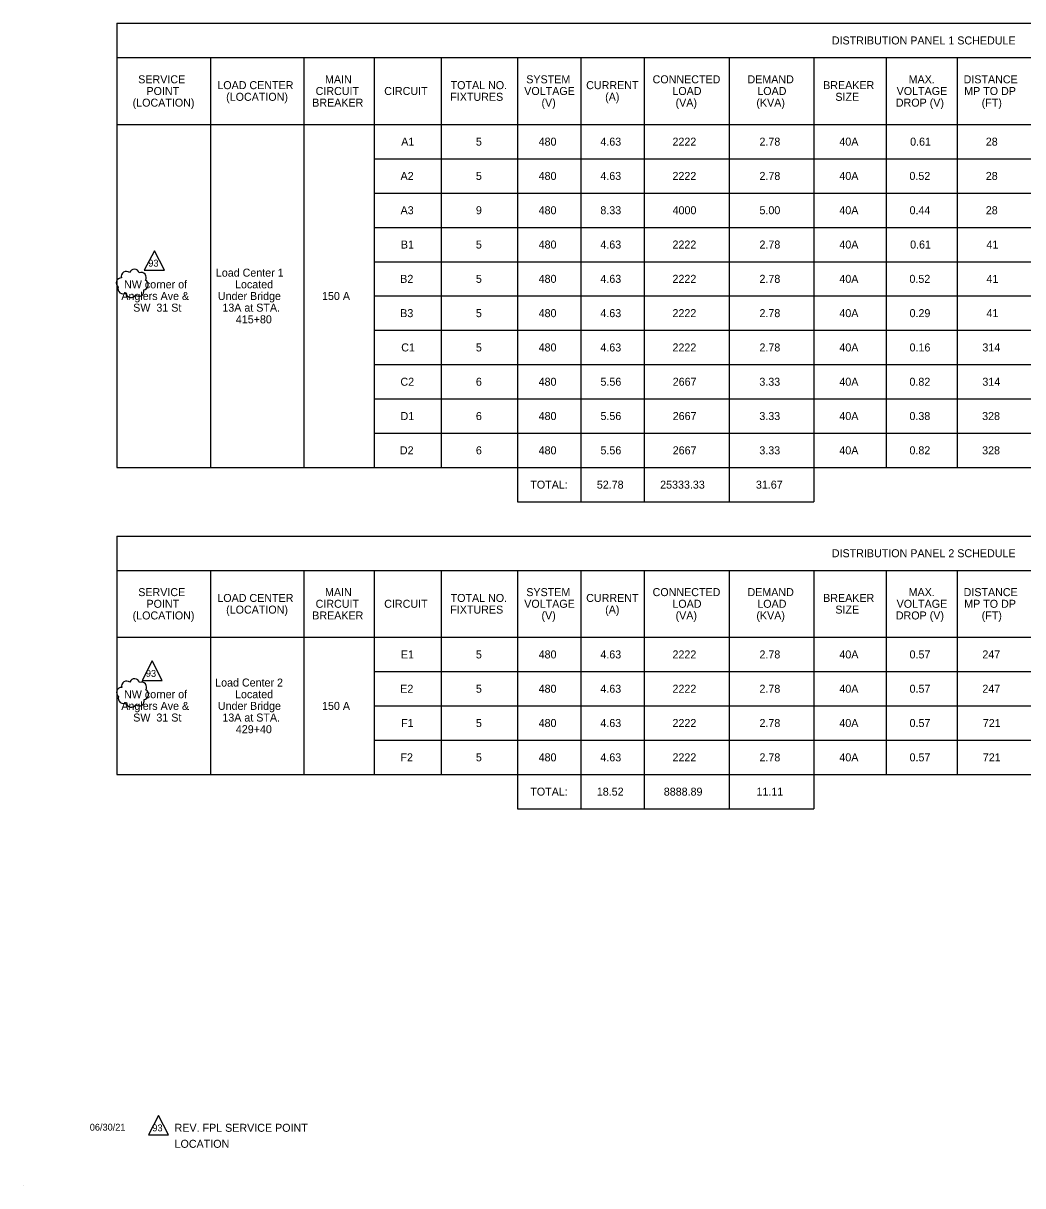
# Model space of a CAD drawing. Extents: x -0.6 to 15.3, y -0.9 to 9.3.
# Drawn here: x -0.55 to 8.19, y -0.9 to 9.27 of the extents above; entities that cross this region are included whole.
import ezdxf

# ---------------------------------------------------------------- set-up
doc = ezdxf.new("R2010")
doc.units = 0
for name, color, linetype in [('AdhocPoint_dp', 7, 'Continuous'), ('Cloud_dp', 7, 'Continuous'), ('SumBoxBorder_dp', 7, 'Continuous'), ('SumBoxLines_dp', 7, 'Continuous'), ('TextLabel', 7, 'Continuous'), ('TextMinor', 7, 'Continuous')]:
    doc.layers.add(name, color=color, linetype=linetype)

msp = doc.modelspace()

# ---------------------------------------------------------------- linework, layer by layer
at = {"layer": 'AdhocPoint_dp'}
msp.add_line((-0.55, -0.9), (-0.55, -0.9), dxfattribs=at)
at = {"layer": 'Cloud_dp'}
for points in [[(0.597, 7.278), (0.509, 7.109), (0.685, 7.109)], [(0.577, 3.69), (0.489, 3.52), (0.665, 3.52)], [(0.633, -0.285), (0.545, -0.454), (0.721, -0.454)]]:
    msp.add_lwpolyline(points, close=True, dxfattribs=at)
for centre, radius, start, end in [((0.308, 6.996), 0.0445, 88.1066, 233.1066), ((0.352, 7.053), 0.0445, 50.9029, 195.9029), ((0.422, 7.072), 0.0445, 15.0691, 160.0691), ((0.482, 7.043), 0.0445, 327.4514, 112.4514), ((0.499, 6.98), 0.0445, 276.583, 61.583), ((0.323, 6.946), 0.0446, 160.4952, 305.4952), ((0.461, 6.924), 0.0445, 229.7011, 14.7011), ((0.394, 6.913), 0.0445, 184.2975, 329.2975), ((0.311, 3.414), 0.0445, 88.1066, 233.1066), ((0.355, 3.47), 0.0445, 50.9029, 195.9029), ((0.425, 3.49), 0.0445, 15.0691, 160.0691), ((0.485, 3.46), 0.0445, 327.4514, 112.4514), ((0.326, 3.363), 0.0446, 160.4952, 305.4952), ((0.502, 3.397), 0.0445, 276.583, 61.583), ((0.397, 3.33), 0.0445, 184.2975, 329.2975), ((0.464, 3.341), 0.0445, 229.7011, 14.7011)]:
    msp.add_arc(centre, radius, start, end, dxfattribs=at)
at = {"layer": 'SumBoxBorder_dp'}
for p, q in [((0.27, 9.267), (14.573, 9.267)), ((0.27, 9.267), (0.27, 5.382)), ((0.27, 8.967), (14.573, 8.967)), ((0.27, 5.382), (14.573, 5.382)), ((0.27, 5.382), (14.573, 5.382)), ((3.773, 5.382), (3.773, 5.082)), ((6.368, 5.382), (6.368, 5.082)), ((6.368, 5.382), (6.368, 5.082)), ((3.773, 5.082), (6.368, 5.082)), ((3.773, 5.082), (6.368, 5.082)), ((0.27, 4.782), (14.573, 4.782)), ((0.27, 4.782), (0.27, 2.697)), ((0.27, 4.482), (14.573, 4.482)), ((0.27, 4.482), (14.573, 4.482)), ((0.27, 2.697), (14.573, 2.697)), ((0.27, 2.697), (14.573, 2.697)), ((3.773, 2.697), (3.773, 2.397)), ((6.368, 2.697), (6.368, 2.397)), ((6.368, 2.697), (6.368, 2.397)), ((3.773, 2.397), (6.368, 2.397))]:
    msp.add_line(p, q, dxfattribs=at)
at = {"layer": 'SumBoxLines_dp'}
for p, q in [((1.088, 8.967), (1.088, 5.382)), ((1.088, 8.967), (1.088, 5.382)), ((1.905, 8.967), (1.905, 5.382)), ((1.905, 8.967), (1.905, 5.382)), ((2.52, 8.967), (2.52, 5.382)), ((2.52, 8.967), (2.52, 5.382)), ((3.105, 8.967), (3.105, 5.382)), ((3.105, 8.967), (3.105, 5.382)), ((3.773, 8.967), (3.773, 5.382)), ((3.773, 8.967), (3.773, 5.382)), ((4.328, 8.967), (4.328, 5.082)), ((4.328, 8.967), (4.328, 5.082)), ((4.883, 8.967), (4.883, 5.082)), ((4.883, 8.967), (4.883, 5.082)), ((5.625, 8.967), (5.625, 5.082)), ((5.625, 8.967), (5.625, 5.082)), ((6.368, 8.967), (6.368, 5.382)), ((6.368, 8.967), (6.368, 5.382)), ((6.998, 8.967), (6.998, 5.382)), ((6.998, 8.967), (6.998, 5.382)), ((7.62, 8.967), (7.62, 5.382)), ((7.62, 8.967), (7.62, 5.382)), ((0.27, 8.382), (14.573, 8.382)), ((0.27, 8.382), (14.573, 8.382)), ((2.52, 8.082), (14.573, 8.082)), ((2.52, 8.082), (14.573, 8.082)), ((2.52, 7.782), (14.573, 7.782)), ((2.52, 7.782), (14.573, 7.782)), ((2.52, 7.482), (14.573, 7.482)), ((2.52, 7.482), (14.573, 7.482)), ((2.52, 7.182), (14.573, 7.182)), ((2.52, 7.182), (14.573, 7.182)), ((2.52, 6.882), (14.573, 6.882)), ((2.52, 6.882), (14.573, 6.882)), ((2.52, 6.582), (14.573, 6.582)), ((2.52, 6.582), (14.573, 6.582)), ((2.52, 6.282), (14.573, 6.282)), ((2.52, 6.282), (14.573, 6.282)), ((2.52, 5.982), (14.573, 5.982)), ((2.52, 5.982), (14.573, 5.982)), ((2.52, 5.682), (14.573, 5.682)), ((2.52, 5.682), (14.573, 5.682)), ((1.088, 4.482), (1.088, 2.697)), ((1.088, 4.482), (1.088, 2.697)), ((1.905, 4.482), (1.905, 2.697)), ((1.905, 4.482), (1.905, 2.697)), ((2.52, 4.482), (2.52, 2.697)), ((2.52, 4.482), (2.52, 2.697)), ((3.105, 4.482), (3.105, 2.697)), ((3.105, 4.482), (3.105, 2.697)), ((3.773, 4.482), (3.773, 2.697)), ((3.773, 4.482), (3.773, 2.697)), ((4.328, 4.482), (4.328, 2.397)), ((4.328, 4.482), (4.328, 2.397)), ((4.883, 4.482), (4.883, 2.397)), ((4.883, 4.482), (4.883, 2.397)), ((5.625, 4.482), (5.625, 2.397)), ((5.625, 4.482), (5.625, 2.397)), ((6.368, 4.482), (6.368, 2.697)), ((6.368, 4.482), (6.368, 2.697)), ((6.998, 4.482), (6.998, 2.697)), ((6.998, 4.482), (6.998, 2.697)), ((7.62, 4.482), (7.62, 2.697)), ((7.62, 4.482), (7.62, 2.697)), ((0.27, 3.897), (14.573, 3.897)), ((0.27, 3.897), (14.573, 3.897)), ((2.52, 3.597), (14.573, 3.597)), ((2.52, 3.597), (14.573, 3.597)), ((2.52, 3.297), (14.573, 3.297)), ((2.52, 3.297), (14.573, 3.297)), ((2.52, 2.997), (14.573, 2.997)), ((2.52, 2.997), (14.573, 2.997))]:
    msp.add_line(p, q, dxfattribs=at)

# ---------------------------------------------------------------- texts
at = {"layer": 'Cloud_dp'}
for p in [(0.544, 7.139), (0.523, 3.551), (0.58, -0.424)]:
    msp.add_text('93', height=0.06, rotation=0, dxfattribs=at).set_placement(p)
at = {"layer": 'TextLabel'}
for s, p in [('DISTRIBUTION PANEL 1 SCHEDULE', (6.524, 9.082)), ('SERVICE', (0.456, 8.742)), ('LOAD CENTER', (1.148, 8.691)), ('MAIN', (2.09, 8.742)), ('TOTAL NO.', (3.189, 8.691)), ('SYSTEM', (3.851, 8.742)), ('CURRENT', (4.375, 8.691)), ('CONNECTED', (4.956, 8.742)), ('DEMAND', (5.786, 8.742)), ('BREAKER', (6.448, 8.691)), ('MAX.', (7.196, 8.742)), ('DISTANCE', (7.677, 8.742)), ('POINT', (0.528, 8.64)), ('(LOCATION)', (1.225, 8.589)), ('CIRCUIT', (2.008, 8.64)), ('CIRCUIT', (2.608, 8.64)), ('FIXTURES', (3.186, 8.589)), ('VOLTAGE', (3.833, 8.64)), ('(A)', (4.541, 8.589)), ('LOAD', (5.129, 8.64)), ('LOAD', (5.872, 8.64)), ('SIZE', (6.555, 8.589)), ('VOLTAGE', (7.091, 8.64)), ('MP TO DP', (7.682, 8.64)), ('(LOCATION)', (0.407, 8.538)), ('BREAKER', (1.978, 8.538)), ('(V)', (3.984, 8.538)), ('(VA)', (5.157, 8.538)), ('(KVA)', (5.864, 8.538)), ('DROP (V)', (7.084, 8.538)), ('(FT)', (7.835, 8.538)), ('A1', (2.757, 8.197)), ('5', (3.41, 8.197)), ('480', (3.959, 8.197)), ('4.63', (4.499, 8.197)), ('2222', (5.13, 8.197)), ('2.78', (5.891, 8.197)), ('40A', (6.59, 8.197)), ('0.61', (7.209, 8.197)), ('28', (7.871, 8.197)), ('A2', (2.751, 7.897)), ('5', (3.41, 7.897)), ('480', (3.959, 7.897)), ('4.63', (4.499, 7.897)), ('2222', (5.13, 7.897)), ('2.78', (5.891, 7.897)), ('40A', (6.59, 7.897)), ('0.52', (7.203, 7.897)), ('28', (7.871, 7.897)), ('A3', (2.751, 7.597)), ('9', (3.41, 7.597)), ('480', (3.959, 7.597)), ('8.33', (4.499, 7.597)), ('4000', (5.131, 7.597)), ('5.00', (5.891, 7.597)), ('40A', (6.59, 7.597)), ('0.44', (7.204, 7.597)), ('28', (7.871, 7.597)), ('B1', (2.754, 7.297)), ('5', (3.41, 7.297)), ('480', (3.959, 7.297)), ('4.63', (4.499, 7.297)), ('2222', (5.13, 7.297)), ('2.78', (5.891, 7.297)), ('40A', (6.59, 7.297)), ('0.61', (7.209, 7.297)), ('41', (7.877, 7.297)), ('Load Center 1', (1.135, 7.051)), ('NW corner of', (0.332, 6.949)), ('Located', (1.303, 6.949)), ('B2', (2.748, 6.997)), ('5', (3.41, 6.997)), ('480', (3.959, 6.997)), ('4.63', (4.499, 6.997)), ('2222', (5.13, 6.997)), ('2.78', (5.891, 6.997)), ('40A', (6.59, 6.997)), ('0.52', (7.203, 6.997)), ('41', (7.877, 6.997)), ('Anglers Ave &', (0.308, 6.847)), ('Under Bridge', (1.153, 6.847)), ('150 A', (2.064, 6.847)), ('SW  31 St', (0.412, 6.745)), ('13A at STA.', (1.192, 6.745)), ('415+80', (1.31, 6.643)), ('B3', (2.748, 6.697)), ('5', (3.41, 6.697)), ('480', (3.959, 6.697)), ('4.63', (4.499, 6.697)), ('2222', (5.13, 6.697)), ('2.78', (5.891, 6.697)), ('40A', (6.59, 6.697)), ('0.29', (7.204, 6.697)), ('41', (7.877, 6.697)), ('C1', (2.757, 6.397)), ('5', (3.41, 6.397)), ('480', (3.959, 6.397)), ('4.63', (4.499, 6.397)), ('2222', (5.13, 6.397)), ('2.78', (5.891, 6.397)), ('40A', (6.59, 6.397)), ('0.16', (7.204, 6.397)), ('314', (7.841, 6.397)), ('C2', (2.75, 6.097)), ('6', (3.41, 6.097)), ('480', (3.959, 6.097)), ('5.56', (4.5, 6.097)), ('2667', (5.132, 6.097)), ('3.33', (5.89, 6.097)), ('40A', (6.59, 6.097)), ('0.82', (7.203, 6.097)), ('314', (7.841, 6.097)), ('D1', (2.751, 5.797)), ('6', (3.41, 5.797)), ('480', (3.959, 5.797)), ('5.56', (4.5, 5.797)), ('2667', (5.132, 5.797)), ('3.33', (5.89, 5.797)), ('40A', (6.59, 5.797)), ('0.38', (7.203, 5.797)), ('328', (7.839, 5.797)), ('D2', (2.745, 5.497)), ('6', (3.41, 5.497)), ('480', (3.959, 5.497)), ('5.56', (4.5, 5.497)), ('2667', (5.132, 5.497)), ('3.33', (5.89, 5.497)), ('40A', (6.59, 5.497)), ('0.82', (7.203, 5.497)), ('328', (7.839, 5.497)), ('TOTAL:', (3.886, 5.197)), ('52.78', (4.468, 5.197)), ('25333.33', (5.022, 5.197)), ('31.67', (5.86, 5.197)), ('DISTRIBUTION PANEL 2 SCHEDULE', (6.524, 4.597)), ('SERVICE', (0.456, 4.257)), ('LOAD CENTER', (1.148, 4.206)), ('MAIN', (2.09, 4.257)), ('TOTAL NO.', (3.189, 4.206)), ('SYSTEM', (3.851, 4.257)), ('CURRENT', (4.375, 4.206)), ('CONNECTED', (4.956, 4.257)), ('DEMAND', (5.786, 4.257)), ('BREAKER', (6.448, 4.206)), ('MAX.', (7.196, 4.257)), ('DISTANCE', (7.677, 4.257)), ('POINT', (0.528, 4.155)), ('(LOCATION)', (1.225, 4.104)), ('CIRCUIT', (2.008, 4.155)), ('CIRCUIT', (2.608, 4.155)), ('FIXTURES', (3.186, 4.104)), ('VOLTAGE', (3.833, 4.155)), ('(A)', (4.541, 4.104)), ('LOAD', (5.129, 4.155)), ('LOAD', (5.872, 4.155)), ('SIZE', (6.555, 4.104)), ('VOLTAGE', (7.091, 4.155)), ('MP TO DP', (7.682, 4.155)), ('(LOCATION)', (0.407, 4.053)), ('BREAKER', (1.978, 4.053)), ('(V)', (3.984, 4.053)), ('(VA)', (5.157, 4.053)), ('(KVA)', (5.864, 4.053)), ('DROP (V)', (7.084, 4.053)), ('(FT)', (7.835, 4.053)), ('E1', (2.754, 3.712)), ('5', (3.41, 3.712)), ('480', (3.959, 3.712)), ('4.63', (4.499, 3.712)), ('2222', (5.13, 3.712)), ('2.78', (5.891, 3.712)), ('40A', (6.59, 3.712)), ('0.57', (7.204, 3.712)), ('247', (7.841, 3.712)), ('Load Center 2', (1.129, 3.466)), ('E2', (2.748, 3.412)), ('5', (3.41, 3.412)), ('480', (3.959, 3.412)), ('4.63', (4.499, 3.412)), ('2222', (5.13, 3.412)), ('2.78', (5.891, 3.412)), ('40A', (6.59, 3.412)), ('0.57', (7.204, 3.412)), ('247', (7.841, 3.412)), ('NW corner of', (0.332, 3.364)), ('Located', (1.303, 3.364)), ('Anglers Ave &', (0.308, 3.262)), ('Under Bridge', (1.153, 3.262)), ('150 A', (2.064, 3.262)), ('SW  31 St', (0.412, 3.16)), ('13A at STA.', (1.192, 3.16)), ('F1', (2.756, 3.112)), ('5', (3.41, 3.112)), ('480', (3.959, 3.112)), ('4.63', (4.499, 3.112)), ('2222', (5.13, 3.112)), ('2.78', (5.891, 3.112)), ('40A', (6.59, 3.112)), ('0.57', (7.204, 3.112)), ('721', (7.845, 3.112)), ('429+40', (1.31, 3.058)), ('F2', (2.75, 2.812)), ('5', (3.41, 2.812)), ('480', (3.959, 2.812)), ('4.63', (4.499, 2.812)), ('2222', (5.13, 2.812)), ('2.78', (5.891, 2.812)), ('40A', (6.59, 2.812)), ('0.57', (7.204, 2.812)), ('721', (7.845, 2.812)), ('TOTAL:', (3.886, 2.512)), ('18.52', (4.468, 2.512)), ('8888.89', (5.054, 2.512)), ('11.11', (5.865, 2.512))]:
    msp.add_text(s, height=0.07, dxfattribs=at).set_placement(p)
at = {"layer": 'TextMinor'}
for s, height, p in [('06/30/21', 0.06, (0.032, -0.418)), ('REV. FPL SERVICE POINT ', 0.07, (0.774, -0.428)), ('LOCATION', 0.07, (0.774, -0.568))]:
    msp.add_text(s, height=height, dxfattribs=at).set_placement(p)

doc.saveas('drawing.dxf')
